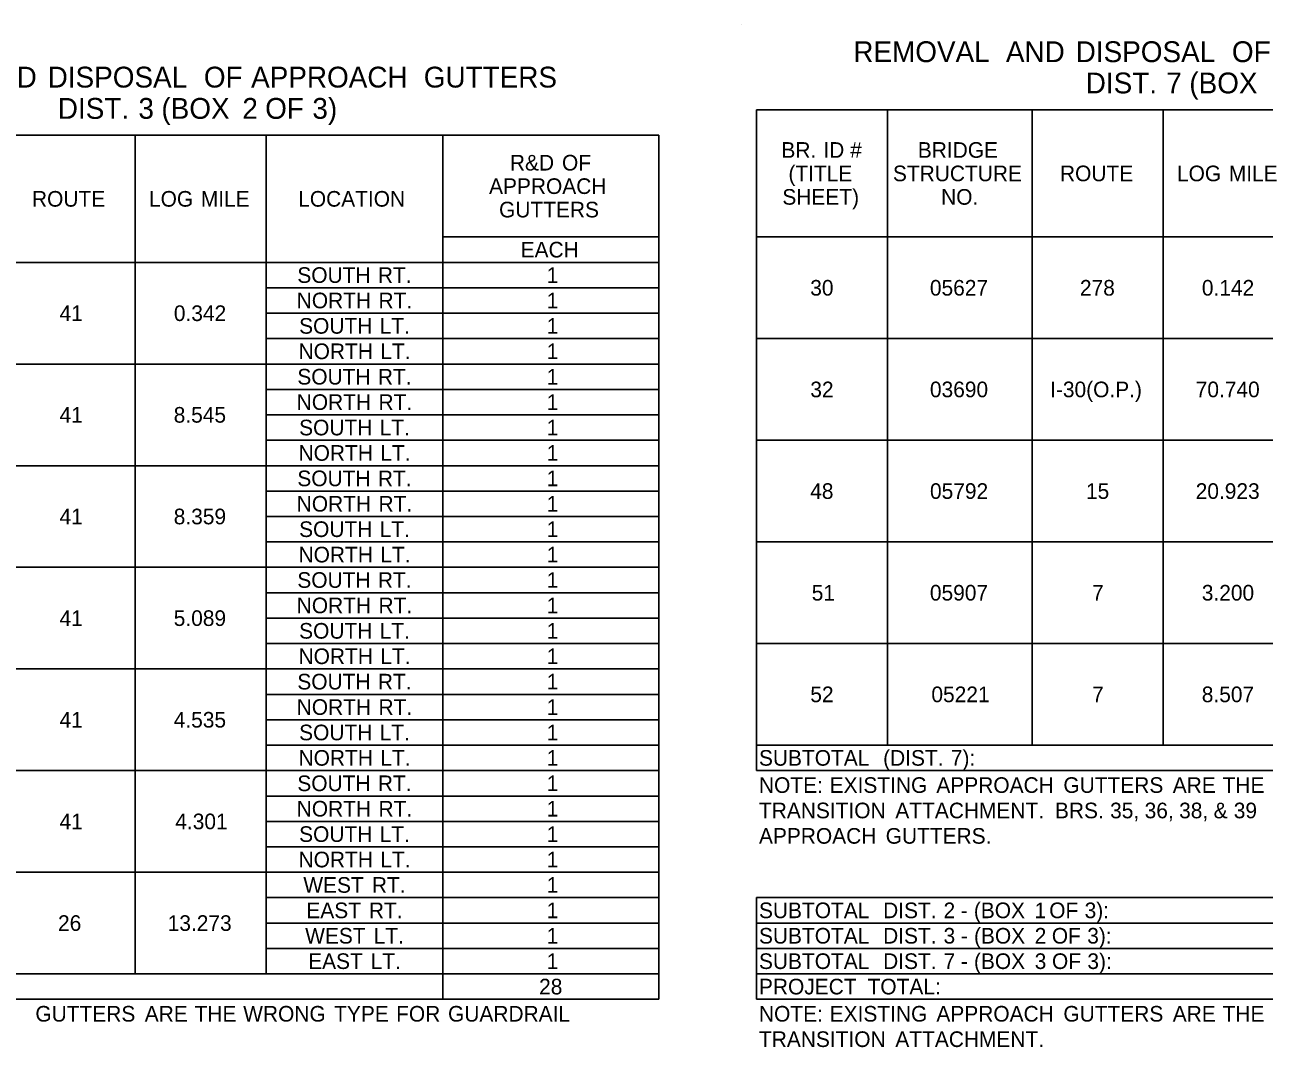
# Model space of a CAD drawing. Extents: x 544250 to 1930787, y -1948365 to 596640.
# Drawn here: x 554242.3 to 554717.7, y -1947711.1 to -1947318.8 of the extents above; entities that cross this region are included whole.
import ezdxf

# ---------------------------------------------------------------- set-up
doc = ezdxf.new("R2010")
doc.units = 0
doc.layers.add('Default', color=7, linetype='Continuous')

msp = doc.modelspace()

# ---------------------------------------------------------------- linework, layer by layer
at = {"layer": 'Default'}
for p, q in [((554517.11, -1947318.76), (554517.11, -1947318.76)), ((554522.96, -1947351.42), (554879.81, -1947351.42)), ((554522.96, -1947604.92), (554522.96, -1947351.42)), ((554522.96, -1947604.92), (554522.96, -1947351.42)), ((554573.18, -1947595.17), (554573.18, -1947351.42)), ((554628.75, -1947595.17), (554628.75, -1947351.42)), ((554678.96, -1947595.17), (554678.96, -1947351.42)), ((554128.67, -1947361.17), (554485.52, -1947361.17)), ((554284.67, -1947682.92), (554284.67, -1947361.17)), ((554334.88, -1947682.92), (554334.88, -1947361.17)), ((554402.64, -1947692.67), (554402.64, -1947361.17)), ((554485.52, -1947692.67), (554485.52, -1947361.17)), ((554485.52, -1947692.67), (554485.52, -1947361.17)), ((554402.64, -1947400.17), (554485.52, -1947400.17)), ((554402.64, -1947400.17), (554485.52, -1947400.17)), ((554522.96, -1947400.17), (554879.81, -1947400.17)), ((554128.67, -1947409.92), (554485.52, -1947409.92)), ((554334.88, -1947419.67), (554485.52, -1947419.67)), ((554334.88, -1947429.42), (554485.52, -1947429.42)), ((554334.88, -1947439.17), (554485.52, -1947439.17)), ((554522.96, -1947439.17), (554879.81, -1947439.17)), ((554128.67, -1947448.92), (554485.52, -1947448.92)), ((554334.88, -1947458.67), (554485.52, -1947458.67)), ((554334.88, -1947468.42), (554485.52, -1947468.42)), ((554334.88, -1947478.17), (554485.52, -1947478.17)), ((554522.96, -1947478.17), (554879.81, -1947478.17)), ((554128.67, -1947487.92), (554485.52, -1947487.92)), ((554334.88, -1947497.67), (554485.52, -1947497.67)), ((554334.88, -1947507.42), (554485.52, -1947507.42)), ((554334.88, -1947517.17), (554485.52, -1947517.17)), ((554522.96, -1947517.17), (554879.81, -1947517.17)), ((554128.67, -1947526.92), (554485.52, -1947526.92)), ((554334.88, -1947536.67), (554485.52, -1947536.67)), ((554334.88, -1947546.42), (554485.52, -1947546.42)), ((554334.88, -1947556.17), (554485.52, -1947556.17)), ((554522.96, -1947556.17), (554879.81, -1947556.17)), ((554128.67, -1947565.92), (554485.52, -1947565.92)), ((554334.88, -1947575.67), (554485.52, -1947575.67)), ((554334.88, -1947585.42), (554485.52, -1947585.42)), ((554334.88, -1947595.17), (554485.52, -1947595.17)), ((554522.96, -1947595.17), (554879.81, -1947595.17)), ((554128.67, -1947604.92), (554485.52, -1947604.92)), ((554522.96, -1947604.92), (554879.81, -1947604.92)), ((554334.88, -1947614.67), (554485.52, -1947614.67)), ((554334.88, -1947624.42), (554485.52, -1947624.42)), ((554334.88, -1947634.17), (554485.52, -1947634.17)), ((554128.67, -1947643.92), (554485.52, -1947643.92)), ((554334.88, -1947653.67), (554485.52, -1947653.67)), ((554522.96, -1947653.67), (554879.81, -1947653.67)), ((554522.96, -1947653.67), (554879.81, -1947653.67)), ((554522.96, -1947692.67), (554522.96, -1947653.67)), ((554522.96, -1947692.67), (554522.96, -1947653.67)), ((554334.88, -1947663.42), (554485.52, -1947663.42)), ((554522.96, -1947663.42), (554879.81, -1947663.42)), ((554334.88, -1947673.17), (554485.52, -1947673.17)), ((554522.96, -1947673.17), (554879.81, -1947673.17)), ((554128.67, -1947682.92), (554485.52, -1947682.92)), ((554522.96, -1947682.92), (554879.81, -1947682.92)), ((554128.67, -1947692.67), (554485.52, -1947692.67)), ((554522.96, -1947692.67), (554879.81, -1947692.67))]:
    msp.add_line(p, q, dxfattribs=at)

# ---------------------------------------------------------------- texts
for s, height, p in [('REMOVAL', 8, (554560.12, -1947333.09)), (' AND', 8, (554615.68, -1947333.09)), (' DISPOSAL', 8, (554642.45, -1947333.09)), (' OF', 8, (554702.36, -1947333.09)), (' AND', 8, (554221.38, -1947342.84)), (' DISPOSAL', 8, (554248.15, -1947342.84)), (' OF', 8, (554308.06, -1947342.84)), (' APPROACH', 8, (554326.17, -1947342.84)), (' GUTTERS', 8, (554392.39, -1947342.84)), (' DIST.', 8, (554646.31, -1947345.09)), (' 7', 8, (554677.21, -1947345.09)), (' (BOX', 8, (554686.03, -1947345.09)), (' DIST.', 8, (554252.04, -1947354.84)), (' 3', 8, (554282.95, -1947354.84)), (' (BOX', 8, (554291.78, -1947354.84)), (' 2', 8, (554322.82, -1947354.84)), (' OF', 8, (554331.57, -1947354.84)), (' 3)', 8, (554349.68, -1947354.84)), ('BR.', 6, (554532.55, -1947369.79)), (' ID', 6, (554546.41, -1947369.79)), (' #', 6, (554556.7, -1947369.79)), ('BRIDGE', 6, (554584.87, -1947369.79)), ('R&D', 6, (554428.41, -1947374.67)), (' OF', 6, (554446.16, -1947374.67)), ('(TITLE', 6, (554535.24, -1947378.79)), ('STRUCTURE', 6, (554575.32, -1947378.79)), ('ROUTE', 6, (554639.39, -1947378.79)), ('LOG', 6, (554684.27, -1947378.79)), (' MILE', 6, (554701.93, -1947378.79)), ('APPROACH', 6, (554420.41, -1947383.67)), ('SHEET)', 6, (554532.91, -1947387.79)), ('NO.', 6, (554593.8, -1947387.79)), ('ROUTE', 6, (554245.1, -1947388.54)), ('LOG', 6, (554289.98, -1947388.54)), (' MILE', 6, (554307.63, -1947388.54)), ('LOCATION', 6, (554347.21, -1947388.54)), ('GUTTERS', 6, (554424.25, -1947392.67)), ('EACH', 6, (554432.52, -1947408.04)), ('SOUTH', 6, (554346.88, -1947417.79)), (' RT.', 6, (554375.54, -1947417.79)), ('1', 6, (554442.52, -1947417.79)), ('30', 6, (554543.61, -1947422.67)), ('05627', 6, (554589.5, -1947422.67)), ('278', 6, (554647.05, -1947422.67)), ('0.142', 6, (554693.81, -1947422.67)), ('NORTH', 6, (554346.64, -1947427.54)), (' RT.', 6, (554375.78, -1947427.54)), ('1', 6, (554442.52, -1947427.54)), ('41', 6, (554255.67, -1947432.42)), ('0.342', 6, (554299.51, -1947432.42)), ('SOUTH', 6, (554347.57, -1947437.29)), (' LT.', 6, (554376.24, -1947437.29)), ('1', 6, (554442.52, -1947437.29)), ('NORTH', 6, (554347.34, -1947447.04)), (' LT.', 6, (554376.47, -1947447.04)), ('1', 6, (554442.52, -1947447.04)), ('SOUTH', 6, (554346.88, -1947456.79)), (' RT.', 6, (554375.54, -1947456.79)), ('1', 6, (554442.52, -1947456.79)), ('32', 6, (554543.63, -1947461.67)), ('03690', 6, (554589.51, -1947461.67)), ('I-30(O.P.)', 6, (554635.61, -1947461.67)), ('70.740', 6, (554691.46, -1947461.67)), ('NORTH', 6, (554346.64, -1947466.54)), (' RT.', 6, (554375.78, -1947466.54)), ('1', 6, (554442.52, -1947466.54)), ('41', 6, (554255.67, -1947471.42)), ('8.545', 6, (554299.46, -1947471.42)), ('SOUTH', 6, (554347.57, -1947476.29)), (' LT.', 6, (554376.24, -1947476.29)), ('1', 6, (554442.52, -1947476.29)), ('NORTH', 6, (554347.34, -1947486.04)), (' LT.', 6, (554376.47, -1947486.04)), ('1', 6, (554442.52, -1947486.04)), ('SOUTH', 6, (554346.88, -1947495.79)), (' RT.', 6, (554375.54, -1947495.79)), ('1', 6, (554442.52, -1947495.79)), ('48', 6, (554543.59, -1947500.67)), ('05792', 6, (554589.54, -1947500.67)), ('15', 6, (554649.36, -1947500.67)), ('20.923', 6, (554691.45, -1947500.67)), ('NORTH', 6, (554346.64, -1947505.54)), (' RT.', 6, (554375.78, -1947505.54)), ('1', 6, (554442.52, -1947505.54)), ('41', 6, (554255.67, -1947510.42)), ('8.359', 6, (554299.47, -1947510.42)), ('SOUTH', 6, (554347.57, -1947515.29)), (' LT.', 6, (554376.24, -1947515.29)), ('1', 6, (554442.52, -1947515.29)), ('NORTH', 6, (554347.34, -1947525.04)), (' LT.', 6, (554376.47, -1947525.04)), ('1', 6, (554442.52, -1947525.04)), ('SOUTH', 6, (554346.88, -1947534.79)), (' RT.', 6, (554375.54, -1947534.79)), ('1', 6, (554442.52, -1947534.79)), ('51', 6, (554544.18, -1947539.67)), ('05907', 6, (554589.5, -1947539.67)), ('7', 6, (554651.72, -1947539.67)), ('3.200', 6, (554693.79, -1947539.67)), ('NORTH', 6, (554346.64, -1947544.54)), (' RT.', 6, (554375.78, -1947544.54)), ('1', 6, (554442.52, -1947544.54)), ('41', 6, (554255.67, -1947549.42)), ('5.089', 6, (554299.47, -1947549.42)), ('SOUTH', 6, (554347.57, -1947554.29)), (' LT.', 6, (554376.24, -1947554.29)), ('1', 6, (554442.52, -1947554.29)), ('NORTH', 6, (554347.34, -1947564.04)), (' LT.', 6, (554376.47, -1947564.04)), ('1', 6, (554442.52, -1947564.04)), ('SOUTH', 6, (554346.88, -1947573.79)), (' RT.', 6, (554375.54, -1947573.79)), ('1', 6, (554442.52, -1947573.79)), ('52', 6, (554543.63, -1947578.67)), ('05221', 6, (554590.08, -1947578.67)), ('7', 6, (554651.72, -1947578.67)), ('8.507', 6, (554693.78, -1947578.67)), ('NORTH', 6, (554346.64, -1947583.54)), (' RT.', 6, (554375.78, -1947583.54)), ('1', 6, (554442.52, -1947583.54)), ('41', 6, (554255.67, -1947588.42)), ('4.535', 6, (554299.46, -1947588.42)), ('SOUTH', 6, (554347.57, -1947593.29)), (' LT.', 6, (554376.24, -1947593.29)), ('1', 6, (554442.52, -1947593.29)), ('NORTH', 6, (554347.34, -1947603.04)), (' LT.', 6, (554376.47, -1947603.04)), ('1', 6, (554442.52, -1947603.04)), ('SUBTOTAL', 6, (554523.94, -1947603.04)), (' (DIST.', 6, (554569.33, -1947603.04)), (' 7):', 6, (554595.3, -1947603.04)), ('SOUTH', 6, (554346.88, -1947612.79)), (' RT.', 6, (554375.54, -1947612.79)), ('1', 6, (554442.52, -1947612.79)), ('NOTE:', 6, (554523.94, -1947613.47)), (' EXISTING', 6, (554548.83, -1947613.47)), (' APPROACH', 6, (554589.76, -1947613.47)), (' GUTTERS', 6, (554638.47, -1947613.47)), (' ARE', 6, (554680.42, -1947613.47)), (' THE', 6, (554699.54, -1947613.47)), ('NORTH', 6, (554346.64, -1947622.54)), (' RT.', 6, (554375.78, -1947622.54)), ('1', 6, (554442.52, -1947622.54)), ('TRANSITION', 6, (554523.94, -1947623.22)), (' ATTACHMENT.', 6, (554574.02, -1947623.22)), (' BRS.', 6, (554635.24, -1947623.22)), (' 35,', 6, (554656.4, -1947623.22)), (' 36,', 6, (554669.64, -1947623.22)), (' 38,', 6, (554682.87, -1947623.22)), (' &', 6, (554696.1, -1947623.22)), (' 39', 6, (554703.82, -1947623.22)), ('41', 6, (554255.67, -1947627.42)), ('4.301', 6, (554300.06, -1947627.42)), ('SOUTH', 6, (554347.57, -1947632.29)), (' LT.', 6, (554376.24, -1947632.29)), ('1', 6, (554442.52, -1947632.29)), ('APPROACH', 6, (554523.94, -1947632.97)), (' GUTTERS.', 6, (554570.32, -1947632.97)), ('NORTH', 6, (554347.34, -1947642.04)), (' LT.', 6, (554376.47, -1947642.04)), ('1', 6, (554442.52, -1947642.04)), ('WEST', 6, (554349.19, -1947651.79)), (' RT.', 6, (554373.24, -1947651.79)), ('1', 6, (554442.52, -1947651.79)), ('EAST', 6, (554350.34, -1947661.54)), (' RT.', 6, (554372.08, -1947661.54)), ('1', 6, (554442.52, -1947661.54)), ('SUBTOTAL', 6, (554523.94, -1947661.54)), (' DIST.', 6, (554569.33, -1947661.54)), (' 2', 6, (554592.51, -1947661.54)), (' (BOX', 6, (554604.13, -1947661.54)), (' 1', 6, (554627.41, -1947661.54)), (' OF', 6, (554633.04, -1947661.54)), (' 3):', 6, (554646.62, -1947661.54)), ('26', 6, (554255.09, -1947666.42)), ('13.273', 6, (554297.15, -1947666.42)), (' -', 6, (554599.08, -1947661.54)), ('WEST', 6, (554349.88, -1947671.29)), (' LT.', 6, (554373.93, -1947671.29)), ('1', 6, (554442.52, -1947671.29)), ('SUBTOTAL', 6, (554523.94, -1947671.29)), (' DIST.', 6, (554569.33, -1947671.29)), (' 3', 6, (554592.51, -1947671.29)), (' (BOX', 6, (554604.19, -1947671.29)), (' 2', 6, (554627.47, -1947671.29)), (' OF', 6, (554634.04, -1947671.29)), (' 3):', 6, (554647.62, -1947671.29)), (' -', 6, (554599.14, -1947671.29)), ('EAST', 6, (554351.04, -1947681.04)), (' LT.', 6, (554372.77, -1947681.04)), ('1', 6, (554442.52, -1947681.04)), ('SUBTOTAL', 6, (554523.94, -1947681.04)), (' DIST.', 6, (554569.33, -1947681.04)), (' 7', 6, (554592.51, -1947681.04)), (' (BOX', 6, (554604.18, -1947681.04)), (' 3', 6, (554627.46, -1947681.04)), (' OF', 6, (554634.09, -1947681.04)), (' 3):', 6, (554647.67, -1947681.04)), (' -', 6, (554599.13, -1947681.04)), ('28', 6, (554439.61, -1947690.79)), ('PROJECT', 6, (554523.94, -1947690.79)), (' TOTAL:', 6, (554563.36, -1947690.79)), (' GUTTERS', 6, (554244.17, -1947701.22)), (' ARE', 6, (554286.12, -1947701.22)), (' THE', 6, (554305.24, -1947701.22)), (' WRONG', 6, (554323.89, -1947701.22)), (' TYPE', 6, (554358.76, -1947701.22)), (' FOR', 6, (554382.54, -1947701.22)), (' GUARDRAIL', 6, (554402.45, -1947701.22)), ('NOTE:', 6, (554523.94, -1947701.22)), (' EXISTING', 6, (554548.83, -1947701.22)), (' APPROACH', 6, (554589.76, -1947701.22)), (' GUTTERS', 6, (554638.47, -1947701.22)), (' ARE', 6, (554680.42, -1947701.22)), (' THE', 6, (554699.54, -1947701.22)), ('TRANSITION', 6, (554523.94, -1947710.97)), (' ATTACHMENT.', 6, (554574.02, -1947710.97))]:
    msp.add_text(s, height=height, dxfattribs=at).set_placement(p)

doc.saveas('drawing.dxf')
